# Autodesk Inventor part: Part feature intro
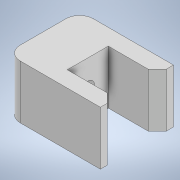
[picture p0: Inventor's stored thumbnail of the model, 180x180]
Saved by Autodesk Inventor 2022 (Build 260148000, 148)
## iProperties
Created: 2019-02
Part Number: Part feature intro
Material: Generic
Document SubType Name: Modeling
Designer: John Helfen
Density: 1 g/cm^3
Appearance: Default
Author: John Helfen
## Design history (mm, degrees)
sketch "Sketch1"
  geometry: L1 (0, 0)-(32.615, 0); L2 (32.615, 0)-(32.615, 18.65); L3 (32.615, 18.65)-(0, 18.65); L4 (0, 18.65)-(0, 0)
  constraints: 8 end point, 2 parallel, 1 horizontal, 1 perpendicular
extrude "Extrusion1" new body sketch "Sketch1" distance "d0" = 25.4; taper "d1" = 0 deg
sketch "Sketch2"
  geometry: L1 (32.615, 0)-(32.615, -25.4) reference; L2 (32.615, -19.892)-(15.599, -19.892); L3 (15.599, -19.892)-(15.599, -5.644); L4 (15.599, -5.644)-(32.615, -5.644); L5 (32.615, -5.644)-(32.615, -19.892); L6 (15.599, -5.644)-(15.599, -0.136); L7 (32.615, -25.4)-(0, -25.4) reference; L8 (15.599, -25.4)-(15.599, -19.892); 2 further points
  constraints: 12 end point, 2 parallel, 2 perpendicular, 2 point on line, 1 collinear, 1 horizontal, 1 vertical
extrude "Extrusion2" cut sketch "Sketch2" extent not by distance; stored distance "d2" = 0; taper "d3" = 0 deg
fillet "Fillet1" dims "d4" = 4.7625
chamfer "Chamfer1" distance "d5" = 3.175; stored, may be unused: second distance "d6" = 3.175, angle "d7" = 45 deg
sketch "Sketch3"
  geometry: L1 (14.248, 0)-(14.248, -18.65) reference; L2 (14.248, -18.65)-(0, 0); 2 further points
  constraints: 2 end point, 1 midpoint
hole "Hole1" sketch "Sketch3" at (7.124, -9.325) diameter "d8" = 3.175; stored, may be unused: countersink angle "d12" = 82 deg, drill point angle "d14" = 118 deg; dims "d9" = 19.05, "d10" = 4.7625, "d11" = 6.35, "d13" = 25.4
body "Solid1"
